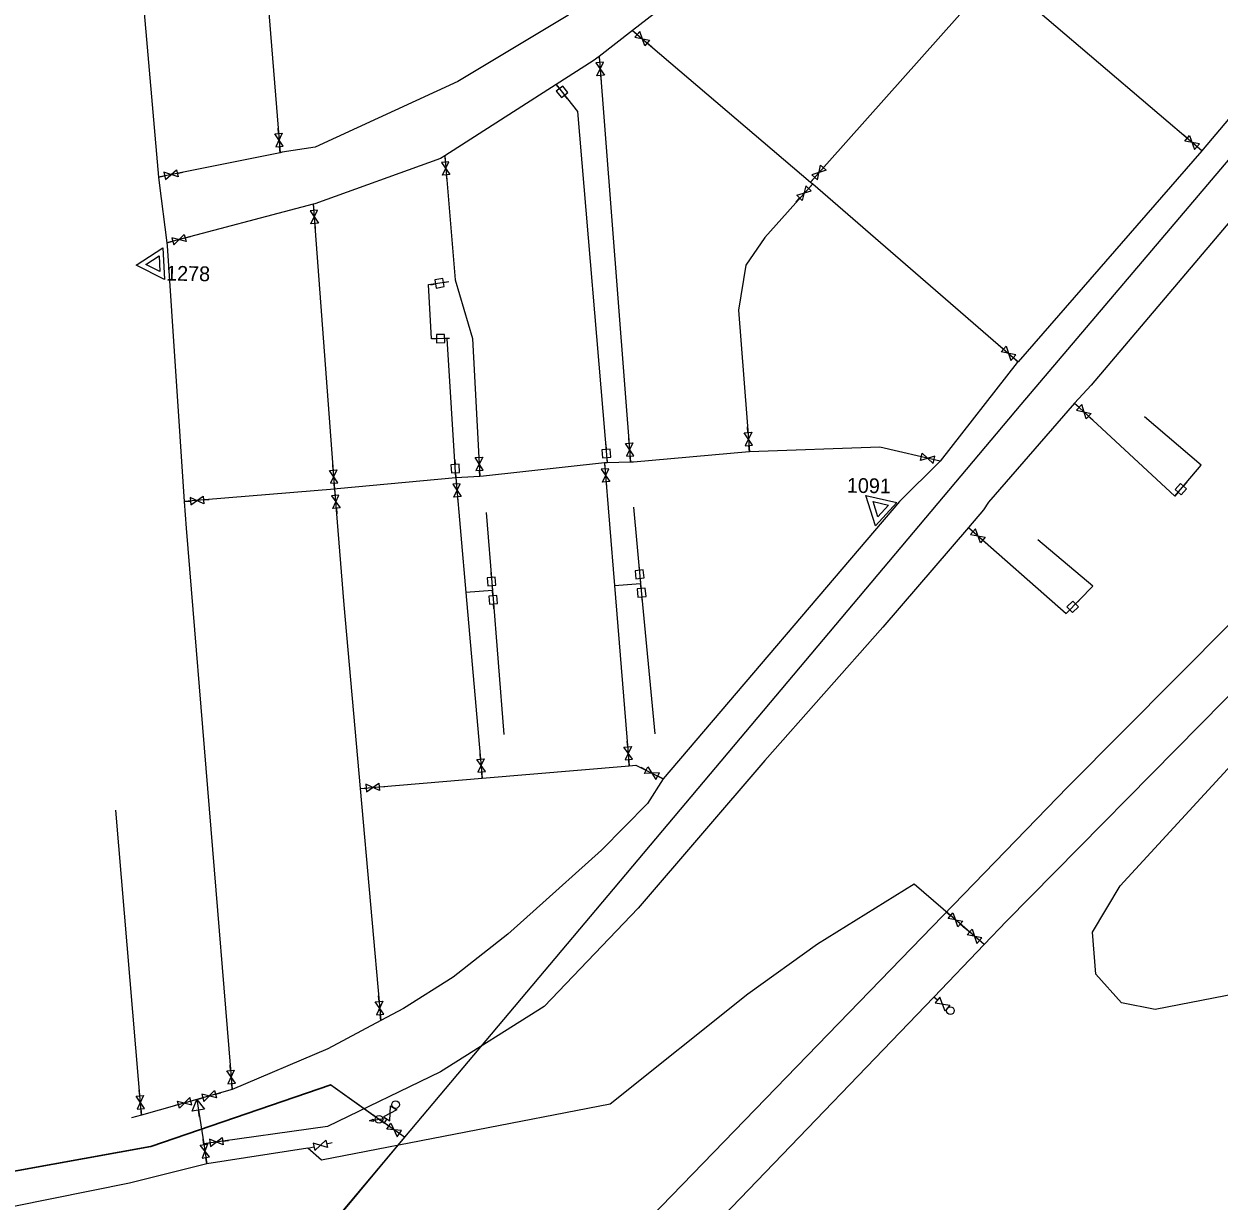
# Model space of a CAD drawing. Extents: x 349903 to 372392, y 368574 to 383062.
# Drawn here: x 363629.9 to 364033.9, y 373000.4 to 373398.5 of the extents above; entities that cross this region are included whole.
import ezdxf

# ---------------------------------------------------------------- set-up
doc = ezdxf.new("R2010")
doc.units = 0
for name, color, linetype in [('Niveau 1', 7, 'Continuous'), ('Niveau 10', 7, 'Continuous'), ('Niveau 2', 7, 'Continuous'), ('Niveau 3', 7, 'Continuous'), ('Niveau 4', 7, 'Continuous'), ('Niveau 5', 7, 'Continuous'), ('Niveau 6', 7, 'Continuous'), ('Niveau 7', 7, 'Continuous')]:
    doc.layers.add(name, color=color, linetype=linetype)

msp = doc.modelspace()

# ---------------------------------------------------------------- linework, layer by layer
at = {"layer": 'Niveau 1'}
for p, q in [((363835.667, 373396.307), (363837.258, 373394.929)), ((363840.568, 373392.063), (363842.007, 373390.818)), ((363824.332, 373387.509), (363824.496, 373385.411)), ((363824.838, 373381.045), (363824.987, 373379.149)), ((363715.963, 373361.389), (363715.808, 373363.284)), ((364023.149, 373359.834), (364021.706, 373361.071)), ((363716.491, 373354.927), (363716.32, 373357.024)), ((364028.071, 373355.613), (364026.474, 373356.983)), ((363772.12, 373353.863), (363772.292, 373351.766)), ((363681.735, 373347.944), (363683.597, 373348.329)), ((363900.136, 373349.863), (363901.401, 373351.282)), ((363675.386, 373346.63), (363677.447, 373347.056)), ((363772.65, 373347.401), (363772.805, 373345.506)), ((363896.55, 373344.401), (363895.108, 373342.868)), ((363895.821, 373345.023), (363897.221, 373346.594)), ((363727.681, 373337.482), (363727.839, 373335.384)), ((363892.109, 373339.677), (363890.807, 373338.291)), ((363728.168, 373331.016), (363728.311, 373329.12)), ((363678.135, 373324.417), (363680.168, 373324.961)), ((363684.398, 373326.094), (363686.235, 373326.586)), ((363961.103, 373288.511), (363959.672, 373289.762)), ((363965.984, 373284.242), (363964.4, 373285.627)), ((363985.065, 373270.259), (363986.608, 373268.828)), ((363989.82, 373265.851), (363991.214, 373264.558)), ((363874.661, 373260.289), (363874.521, 373262.185)), ((363834.481, 373256.703), (363834.333, 373258.599)), ((363875.139, 373253.823), (363874.984, 373255.922)), ((363783.735, 373251.916), (363783.649, 373253.816)), ((363834.988, 373250.239), (363834.824, 373252.337)), ((363933.304, 373252.072), (363931.454, 373252.508)), ((363939.615, 373250.583), (363937.567, 373251.066)), ((363734.403, 373247.604), (363734.259, 373249.5)), ((363784.028, 373245.439), (363783.933, 373247.541)), ((363826.14, 373250.072), (363826.314, 373247.975)), ((363734.894, 373241.139), (363734.735, 373243.237)), ((363775.905, 373244.987), (363776.076, 373242.89)), ((363826.676, 373243.61), (363826.833, 373241.715)), ((363734.894, 373241.139), (363735.099, 373239.045)), ((363684.1, 373236.939), (363686.197, 373237.116)), ((363690.561, 373237.487), (363692.455, 373237.647)), ((363776.433, 373238.525), (363776.588, 373236.63)), ((363735.526, 373234.686), (363735.711, 373232.794)), ((363949.188, 373228.207), (363950.769, 373226.818)), ((363954.06, 373223.928), (363955.488, 373222.674)), ((363833.999, 373154.054), (363833.84, 373155.949)), ((363784.234, 373149.86), (363784.065, 373151.754)), ((363834.544, 373147.593), (363834.368, 373149.69)), ((363840.231, 373146.113), (363838.537, 373146.977)), ((363784.812, 373143.402), (363784.625, 373145.498)), ((363846.007, 373143.167), (363844.133, 373144.123)), ((363743.51, 373139.883), (363745.606, 373140.065)), ((363749.97, 373140.443), (363751.864, 373140.608)), ((363949.604, 373091.375), (363948.171, 373092.624)), ((363954.492, 373087.114), (363952.906, 373088.497)), ((363749.929, 373067.885), (363749.761, 373069.779)), ((363750.501, 373061.426), (363750.316, 373063.522)), ((363699.735, 373044.532), (363699.575, 373046.426)), ((363669.04, 373035.959), (363668.882, 373037.854)), ((363669.04, 373035.959), (363668.882, 373037.854)), ((363694.597, 373036.521), (363696.425, 373037.043)), ((363700.282, 373038.071), (363700.105, 373040.168)), ((363682.115, 373033.007), (363680.283, 373032.498)), ((363688.362, 373034.742), (363686.334, 373034.179)), ((363688.362, 373034.742), (363690.386, 373035.319)), ((363669.405, 373031.604), (363669.581, 373029.498)), ((363669.405, 373031.604), (363669.581, 373029.498)), ((363753.25, 373025.708), (363751.696, 373026.803)), ((363690.726, 373019.435), (363690.443, 373021.315)), ((363697.107, 373020.659), (363698.991, 373020.917)), ((363758.548, 373021.97), (363756.829, 373023.183)), ((363690.683, 373019.78), (363692.768, 373020.065)), ((363725.891, 373018.264), (363727.938, 373018.753)), ((363732.197, 373019.773), (363734.046, 373020.215)), ((363691.691, 373013.023), (363691.378, 373015.104))]:
    msp.add_line(p, q, dxfattribs=at)
for points in [[(363841.395, 373393.024), (363839.751, 373391.112), (363838.099, 373395.879), (363836.44, 373393.977)], [(363826.102, 373381.148), (363823.587, 373380.943), (363825.762, 373385.496), (363823.245, 373385.307)], [(363714.7, 373361.282), (363717.214, 373361.495), (363715.055, 373356.935), (363717.57, 373357.132)], [(364022.327, 373358.868), (364023.963, 373360.789), (364025.638, 373356.029), (364027.286, 373357.94)], [(363681.475, 373349.185), (363681.994, 373346.716), (363677.203, 373348.301), (363677.707, 373345.828)], [(363773.913, 373347.508), (363771.399, 373347.294), (363773.557, 373351.856), (363771.041, 373351.657)], [(363899.186, 373350.704), (363901.075, 373349.031), (363896.284, 373347.448), (363898.162, 373345.763)], [(363893.036, 373338.811), (363891.192, 373340.534), (363896.023, 373341.989), (363894.19, 373343.723)], [(363729.433, 373331.116), (363726.917, 373330.918), (363729.105, 373335.465), (363726.588, 373335.283)], [(363684.066, 373327.318), (363684.727, 373324.882), (363679.853, 373326.19), (363680.498, 373323.75)], [(363960.271, 373287.553), (363961.926, 373289.457), (363963.555, 373284.681), (363965.222, 373286.576)], [(363990.679, 373266.783), (363988.969, 373264.928), (363987.48, 373269.749), (363985.759, 373267.904)], [(363873.397, 373260.192), (363875.913, 373260.386), (363873.718, 373255.842), (363876.236, 373256.02)], [(363833.217, 373256.6), (363835.732, 373256.805), (363833.558, 373252.252), (363836.075, 373252.441)], [(363782.468, 373251.855), (363784.988, 373251.977), (363782.665, 373247.498), (363785.187, 373247.604)], [(363933.017, 373250.837), (363933.589, 373253.294), (363937.262, 373249.835), (363937.849, 373252.289)], [(363733.139, 373247.504), (363735.654, 373247.703), (363733.469, 373243.155), (363735.986, 373243.338)], [(363827.94, 373243.719), (363825.426, 373243.503), (363827.579, 373248.066), (363825.063, 373247.865)], [(363777.697, 373238.632), (363775.182, 373238.418), (363777.341, 373242.979), (363774.826, 373242.782)], [(363736.787, 373234.814), (363734.277, 373234.56), (363736.363, 373239.155), (363733.85, 373238.917)], [(363690.45, 373238.75), (363690.671, 373236.236), (363686.104, 373238.381), (363686.309, 373235.866)], [(363954.893, 373224.884), (363953.234, 373222.983), (363951.616, 373227.762), (363949.945, 373225.871)], [(363832.736, 373153.943), (363835.25, 373154.163), (363833.102, 373149.597), (363835.618, 373149.801)], [(363782.972, 373149.743), (363785.484, 373149.976), (363783.36, 373145.399), (363785.874, 373145.616)], [(363839.658, 373144.982), (363840.798, 373147.233), (363843.544, 373143), (363844.698, 373145.244)], [(363749.856, 373141.706), (363750.082, 373139.193), (363745.511, 373141.329), (363745.721, 373138.815)], [(363948.774, 373090.416), (363950.426, 373092.323), (363952.062, 373087.55), (363953.726, 373089.447)], [(363748.666, 373067.769), (363751.178, 373067.999), (363749.051, 373063.424), (363751.565, 373063.639)], [(363698.472, 373044.421), (363700.986, 373044.642), (363698.84, 373040.075), (363701.355, 373040.28)], [(363694.245, 373037.739), (363694.945, 373035.315), (363690.051, 373036.543), (363690.736, 373034.114)], [(363667.777, 373035.85), (363670.291, 373036.068), (363668.141, 373031.503), (363670.656, 373031.705)], [(363667.777, 373035.85), (363670.291, 373036.068), (363668.141, 373031.503), (363670.656, 373031.705)], [(363682.458, 373031.787), (363681.775, 373034.216), (363686.66, 373032.953), (363685.992, 373035.387)], [(363752.522, 373024.669), (363753.97, 373026.735), (363756.086, 373022.155), (363757.547, 373024.212)], [(363696.931, 373021.915), (363697.281, 373019.416), (363692.61, 373021.324), (363692.944, 373018.822)], [(363731.898, 373021.005), (363732.493, 373018.553), (363727.656, 373019.99), (363728.235, 373017.534)], [(363689.473, 373019.242), (363691.967, 373019.625), (363690.122, 373014.929), (363692.618, 373015.297)]]:
    msp.add_lwpolyline(points, close=True, dxfattribs=at)
at = {"layer": 'Niveau 10'}
for p, q in [((363824.332, 373387.509), (363834.988, 373250.239)), ((363727.681, 373337.482), (363734.894, 373241.139)), ((363985.065, 373270.259), (364018.993, 373238.785)), ((363826.14, 373250.072), (363829.489, 373208.548)), ((363775.905, 373244.987), (363779.308, 373206.221)), ((363835.909, 373235.099), (363838.362, 373209.246)), ((363786.166, 373233.255), (363788.251, 373206.832)), ((363949.188, 373228.207), (363982.242, 373199.136)), ((363788.251, 373206.832), (363779.308, 373206.221)), ((363788.251, 373206.832), (363792.088, 373158.209)), ((363829.489, 373208.548), (363838.362, 373209.246)), ((363829.489, 373208.548), (363834.544, 373147.593)), ((363838.362, 373209.246), (363843.181, 373158.46)), ((363779.308, 373206.221), (363784.812, 373143.402)), ((363982.809, 373140.47), (363794.398, 372946.095)), ((363669.581, 373029.498), (363660.959, 373132.54)), ((363700.282, 373038.071), (363688.362, 373034.742)), ((363688.362, 373034.742), (363669.581, 373029.498)), ((363688.362, 373034.742), (363690.683, 373019.78)), ((363669.581, 373029.498), (363666.184, 373028.549)), ((363690.683, 373019.78), (363691.691, 373013.023)), ((363725.891, 373018.264), (363691.691, 373013.023)), ((363730.445, 373014.211), (363725.891, 373018.264))]:
    msp.add_line(p, q, dxfattribs=at)
for points in [[(366766.936, 376040.549), (366763.46, 376037.341), (366667.812, 375934.705), (366617.063, 375879.047), (366370.17, 375608.973), (366271.904, 375503.403), (366107.898, 375322.357), (365954.331, 375156.168), (365788.236, 374978.178), (365607.938, 374785.446), (365518.975, 374699.397), (365364.307, 374546.897), (365333.229, 374555.57), (364778.418, 374088.297), (364472.26, 373830.629), (364367.399, 373726.809), (364168.973, 373500.723), (364094.413, 373420.15), (363966.939, 373269.827), (363827.246, 373103.73), (363758.548, 373021.97), (363751.696, 373026.803)], [(363659.176, 373543.882), (363668.426, 373426.91), (363675.386, 373346.63)], [(363946.125, 373513.797), (363845.544, 373403.972), (363835.667, 373396.307)], [(363709.695, 373438.487), (363716.491, 373354.927)], [(364028.071, 373355.613), (363958.248, 373415.142), (363895.821, 373345.023)], [(364070.087, 373405.377), (364028.51, 373356.119), (364028.071, 373355.613)], [(363814.259, 373401.787), (363813.789, 373401.346), (363776.525, 373378.972), (363728.361, 373356.851), (363717.207, 373355.071), (363716.491, 373354.927)], [(363835.667, 373396.307), (363824.332, 373387.509)], [(363835.667, 373396.307), (363895.821, 373345.023)], [(363824.332, 373387.509), (363822.362, 373385.98), (363809.843, 373377.977)], [(363809.843, 373377.977), (363772.12, 373353.863)], [(363809.843, 373377.977), (363817.01, 373368.881), (363827.067, 373250.089)], [(363716.491, 373354.927), (363675.386, 373346.63)], [(363772.12, 373353.863), (363770.763, 373352.995), (363728.25, 373337.632), (363727.681, 373337.482)], [(363772.12, 373353.863), (363775.648, 373311.906), (363781.47, 373292.062), (363784.028, 373245.439)], [(364028.071, 373355.613), (363965.984, 373284.242)], [(363675.386, 373346.63), (363675.55, 373344.733), (363678.135, 373324.417)], [(363896.55, 373344.401), (363880.382, 373326.263), (363873.946, 373316.879), (363871.411, 373301.63), (363875.139, 373253.823)], [(363895.821, 373345.023), (363896.55, 373344.401)], [(363896.55, 373344.401), (363965.984, 373284.242)], [(363727.681, 373337.482), (363678.135, 373324.417)], [(364039.803, 373334.226), (364039.522, 373333.883), (363990.705, 373276.356), (363985.065, 373270.259)], [(363678.135, 373324.417), (363678.264, 373323.397), (363684.1, 373236.939)], [(364192.961, 373327.651), (364162.307, 373295.858), (364035.598, 373169.725), (363962.088, 373095.015), (363954.492, 373087.114)], [(363767.615, 373291.974), (363766.69, 373310.322), (363773.469, 373311.321)], [(363775.905, 373244.987), (363773.007, 373292.148), (363767.615, 373291.974)], [(363965.984, 373284.242), (363965.719, 373283.938), (363939.615, 373250.583)], [(364113.667, 373272.153), (364111.574, 373270.083), (363982.809, 373140.47)], [(363985.065, 373270.259), (363955.942, 373236.751), (363954.283, 373234.136), (363949.188, 373228.207)], [(364018.993, 373238.785), (364027.931, 373249.221), (364008.682, 373265.581)], [(363939.615, 373250.583), (363919.249, 373255.403), (363875.139, 373253.823)], [(363875.139, 373253.823), (363875.015, 373253.819), (363835.915, 373250.256), (363834.988, 373250.239)], [(363826.14, 373250.072), (363785.263, 373245.508), (363784.028, 373245.439)], [(363827.067, 373250.089), (363826.14, 373250.072)], [(363834.988, 373250.239), (363827.067, 373250.089)], [(363939.615, 373250.583), (363925.895, 373236.967), (363846.007, 373143.167)], [(363775.905, 373244.987), (363735.757, 373241.21), (363734.894, 373241.139)], [(363784.028, 373245.439), (363775.905, 373244.987)], [(363734.894, 373241.139), (363684.1, 373236.939)], [(363734.894, 373241.139), (363737.975, 373201.996), (363743.51, 373139.883)], [(363684.1, 373236.939), (363684.709, 373227.917), (363700.282, 373038.071)], [(363949.188, 373228.207), (363920.254, 373194.531)], [(363982.242, 373199.136), (363991.287, 373208.298), (363972.613, 373223.996)], [(364150.943, 373092.135), (364012.353, 373065.204), (364000.914, 373067.39), (363992.232, 373077.181), (363991.147, 373091.33), (364000.483, 373107.002), (364096.37, 373211.258)], [(363920.254, 373194.531), (363880.315, 373149.338), (363837.489, 373099.481), (363805.715, 373066.243), (363770.717, 373044.085), (363732.496, 373025.62), (363690.683, 373019.78)], [(363691.691, 373013.023), (363665.555, 373006.438), (363560.368, 372985.3), (363466.328, 372961.975), (363420.763, 372957.116), (363358.717, 372961.975), (363317.999, 372978.497), (363274.757, 373004.932), (363229.192, 373044.806), (363099.863, 373176.5)], [(363751.696, 373026.803), (363748.876, 373028.809), (363733.47, 373039.727), (363672.619, 373018.885), (363672.619, 373018.885), (363594.701, 373004.742), (363503.614, 372982.415), (363459.875, 372971.453), (363408.184, 372966.47), (363353.51, 372972.45), (363281.937, 373012.31), (363221.299, 373070.109), (363131.759, 373165.491)], [(363784.812, 373143.402), (363834.544, 373147.593)], [(363834.544, 373147.593), (363836.798, 373147.783), (363846.007, 373143.167)], [(363743.51, 373139.883), (363784.812, 373143.402)], [(363846.007, 373143.167), (363840.7, 373134.874), (363825.092, 373119.032), (363802.07, 373098.3), (363793.486, 373090.672), (363774.951, 373076.106), (363758.172, 373065.538), (363750.501, 373061.426)], [(363743.51, 373139.883), (363750.501, 373061.426)], [(363954.492, 373087.114), (363930.818, 373107.536), (363898.196, 373087.238), (363874.574, 373070.323), (363828.057, 373033.192), (363730.445, 373014.211)], [(363954.492, 373087.114), (363937.464, 373069.402)], [(363937.464, 373069.402), (363806.543, 372933.223)], [(363750.501, 373061.426), (363732.614, 373051.838), (363700.282, 373038.071)], [(363751.819, 373026.676), (363733.593, 373039.6), (363672.742, 373018.758), (363594.824, 373004.615)], [(363758.548, 373021.97), (363751.696, 373026.803)], [(363758.548, 373021.97), (363387.656, 372576.394), (363076.85, 372194.567), (362987.022, 372096.447), (362639.639, 371713.502), (362501.408, 371562.226)], [(363758.548, 373021.97), (363587.181, 372818.111), (363052.431, 372166.564), (362880.62, 371984.026)]]:
    msp.add_lwpolyline(points, dxfattribs=at)
at = {"layer": 'Niveau 2'}
for points in [[(363676.856, 373322.782), (363677.436, 373312.039), (363667.843, 373316.908)], [(363675.537, 373320.107), (363675.826, 373314.737), (363671.03, 373317.174)], [(363925.036, 373236.646), (363917.731, 373228.747), (363914.543, 373239.021)], [(363922.198, 373235.729), (363918.546, 373231.781), (363916.954, 373236.92)]]:
    msp.add_lwpolyline(points, close=True, dxfattribs=at)
at = {"layer": 'Niveau 3'}
for p, q in [((363810.919, 373376.607), (363809.843, 373377.977)), ((363813.636, 373373.144), (363812.633, 373374.421)), ((363767.413, 373310.286), (363769.015, 373310.56)), ((363771.752, 373311.027), (363773.469, 373311.321)), ((363769.357, 373292.022), (363767.615, 373291.974)), ((363773.757, 373292.141), (363772.133, 373292.096)), ((363826.559, 373256.212), (363826.694, 373254.593)), ((363775.561, 373251.121), (363775.652, 373249.5)), ((363826.923, 373251.825), (363827.067, 373250.089)), ((363775.807, 373246.727), (363775.905, 373244.987)), ((364023.011, 373243.433), (364021.949, 373242.204)), ((364020.132, 373240.103), (364018.993, 373238.785)), ((363837.733, 373215.358), (363837.9, 373213.742)), ((363787.74, 373212.955), (363787.876, 373211.336)), ((363838.183, 373210.979), (363838.362, 373209.246)), ((363788.106, 373208.568), (363788.251, 373206.832)), ((363788.379, 373205.095), (363788.251, 373206.832)), ((363838.528, 373207.512), (363838.362, 373209.246)), ((363838.946, 373203.129), (363838.791, 373204.747)), ((363986.595, 373203.472), (363985.444, 373202.326)), ((363788.703, 373200.704), (363788.583, 373202.325)), ((363983.476, 373200.366), (363982.242, 373199.136))]:
    msp.add_line(p, q, dxfattribs=at)
for points in [[(363812.026, 373377.476), (363809.865, 373375.78), (363811.566, 373373.614), (363813.726, 373375.309)], [(363771.989, 373309.641), (363771.527, 373312.347), (363768.812, 373311.883), (363769.274, 373309.176)], [(363769.318, 373293.428), (363769.392, 373290.683), (363772.146, 373290.757), (363772.071, 373293.503)], [(363825.52, 373251.709), (363828.257, 373251.935), (363828.03, 373254.68), (363825.293, 373254.454)], [(363774.402, 373246.647), (363777.144, 373246.801), (363776.99, 373249.551), (363774.248, 373249.397)], [(364019.067, 373241.023), (364021.145, 373239.227), (364022.946, 373241.311), (364020.868, 373243.107)], [(363786.704, 373208.451), (363789.44, 373208.679), (363789.211, 373211.424), (363786.475, 373211.196)], [(363836.784, 373210.835), (363839.516, 373211.115), (363839.234, 373213.855), (363836.502, 373213.574)], [(363839.928, 373207.645), (363837.194, 373207.386), (363837.456, 373204.644), (363840.19, 373204.904)], [(363789.782, 373205.198), (363787.044, 373204.996), (363787.247, 373202.249), (363789.985, 373202.451)], [(363982.483, 373201.362), (363984.421, 373199.417), (363986.372, 373201.36), (363984.434, 373203.306)]]:
    msp.add_lwpolyline(points, close=True, dxfattribs=at)
at = {"layer": 'Niveau 4'}
for p, q in [((363941.656, 373098.181), (363943.112, 373096.939)), ((363946.445, 373094.097), (363948.171, 373092.624))]:
    msp.add_line(p, q, dxfattribs=at)
for points in [[(363942.293, 373095.971), (363943.923, 373097.896), (363944.775, 373095.521)], [(363944.775, 373095.521), (363947.255, 373095.056), (363945.611, 373093.141)]]:
    msp.add_lwpolyline(points, close=True, dxfattribs=at)
at = {"layer": 'Niveau 5'}
msp.add_line((363689.195, 373028.788), (363688.869, 373031.12), dxfattribs=at)
msp.add_lwpolyline([(363688.362, 373034.742), (363690.939, 373031.419), (363686.772, 373030.85)], close=True, dxfattribs=at)
at = {"layer": 'Niveau 6'}
for p, q in [((363938.7, 373068.388), (363937.464, 373069.402)), ((363752.535, 373028.163), (363751.696, 373026.803))]:
    msp.add_line(p, q, dxfattribs=at)
for points in [[(363942.887, 373066.595), (363941.293, 373064.639), (363939.515, 373069.36), (363937.908, 373067.414)], [(363753.753, 373032.552), (363755.905, 373031.234), (363751.463, 373028.841), (363753.607, 373027.509)]]:
    msp.add_lwpolyline(points, close=True, dxfattribs=at)
for centre in [(363943.121, 373064.787), (363755.513, 373033.027)]:
    msp.add_circle(centre, 1.29, dxfattribs=at)
at = {"layer": 'Niveau 7'}
for p, q in [((363748.876, 373028.809), (363748.024, 373029.413)), ((363747.851, 373027.705), (363751.647, 373028.357)), ((363750.994, 373027.299), (363751.696, 373026.803))]:
    msp.add_line(p, q, dxfattribs=at)
msp.add_lwpolyline([(363748.026, 373027.331), (363746.67, 373027.572), (363747.893, 373028.112)], close=True, dxfattribs=at)
msp.add_circle((363749.932, 373028.051), 1.301, dxfattribs=at)

# ---------------------------------------------------------------- texts
at = {"layer": 'Niveau 2'}
for s, p in [('1278', (363677.901, 373311.707)), ('1091', (363908.055, 373239.958))]:
    msp.add_text(s, height=5, rotation=359, dxfattribs=at).set_placement(p)

doc.saveas('drawing.dxf')
